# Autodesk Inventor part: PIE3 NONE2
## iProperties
Shininess: 64.0
Length Units: 11269
Angle Units: 11279
Time Units: 11290
Mass Units: 11286
Length Display Precision: 3
Angle Display Precision: 2
Compacted: True
Part Number: PIE3 NONE2
Document SubType Name: Modeling
Created: 2004-08
Designer: John Blackburn
Manufacturer: Standard
Standards Organization: Custom
Density: 0.0
Volumn: 0.0
Area: 0.0
PropertySet Name: Model Information
Control State: 0
Master: False
Checked Out: False
Author: John Blackburn
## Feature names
1. Erst1
